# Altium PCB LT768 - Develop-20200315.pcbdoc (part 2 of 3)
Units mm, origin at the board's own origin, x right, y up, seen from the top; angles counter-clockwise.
Board outline 114.72 x 114.74 mm, 2 copper layers (Top Layer, Bottom Layer); 164 components, 138 nets, 704 pads, 858 vias.
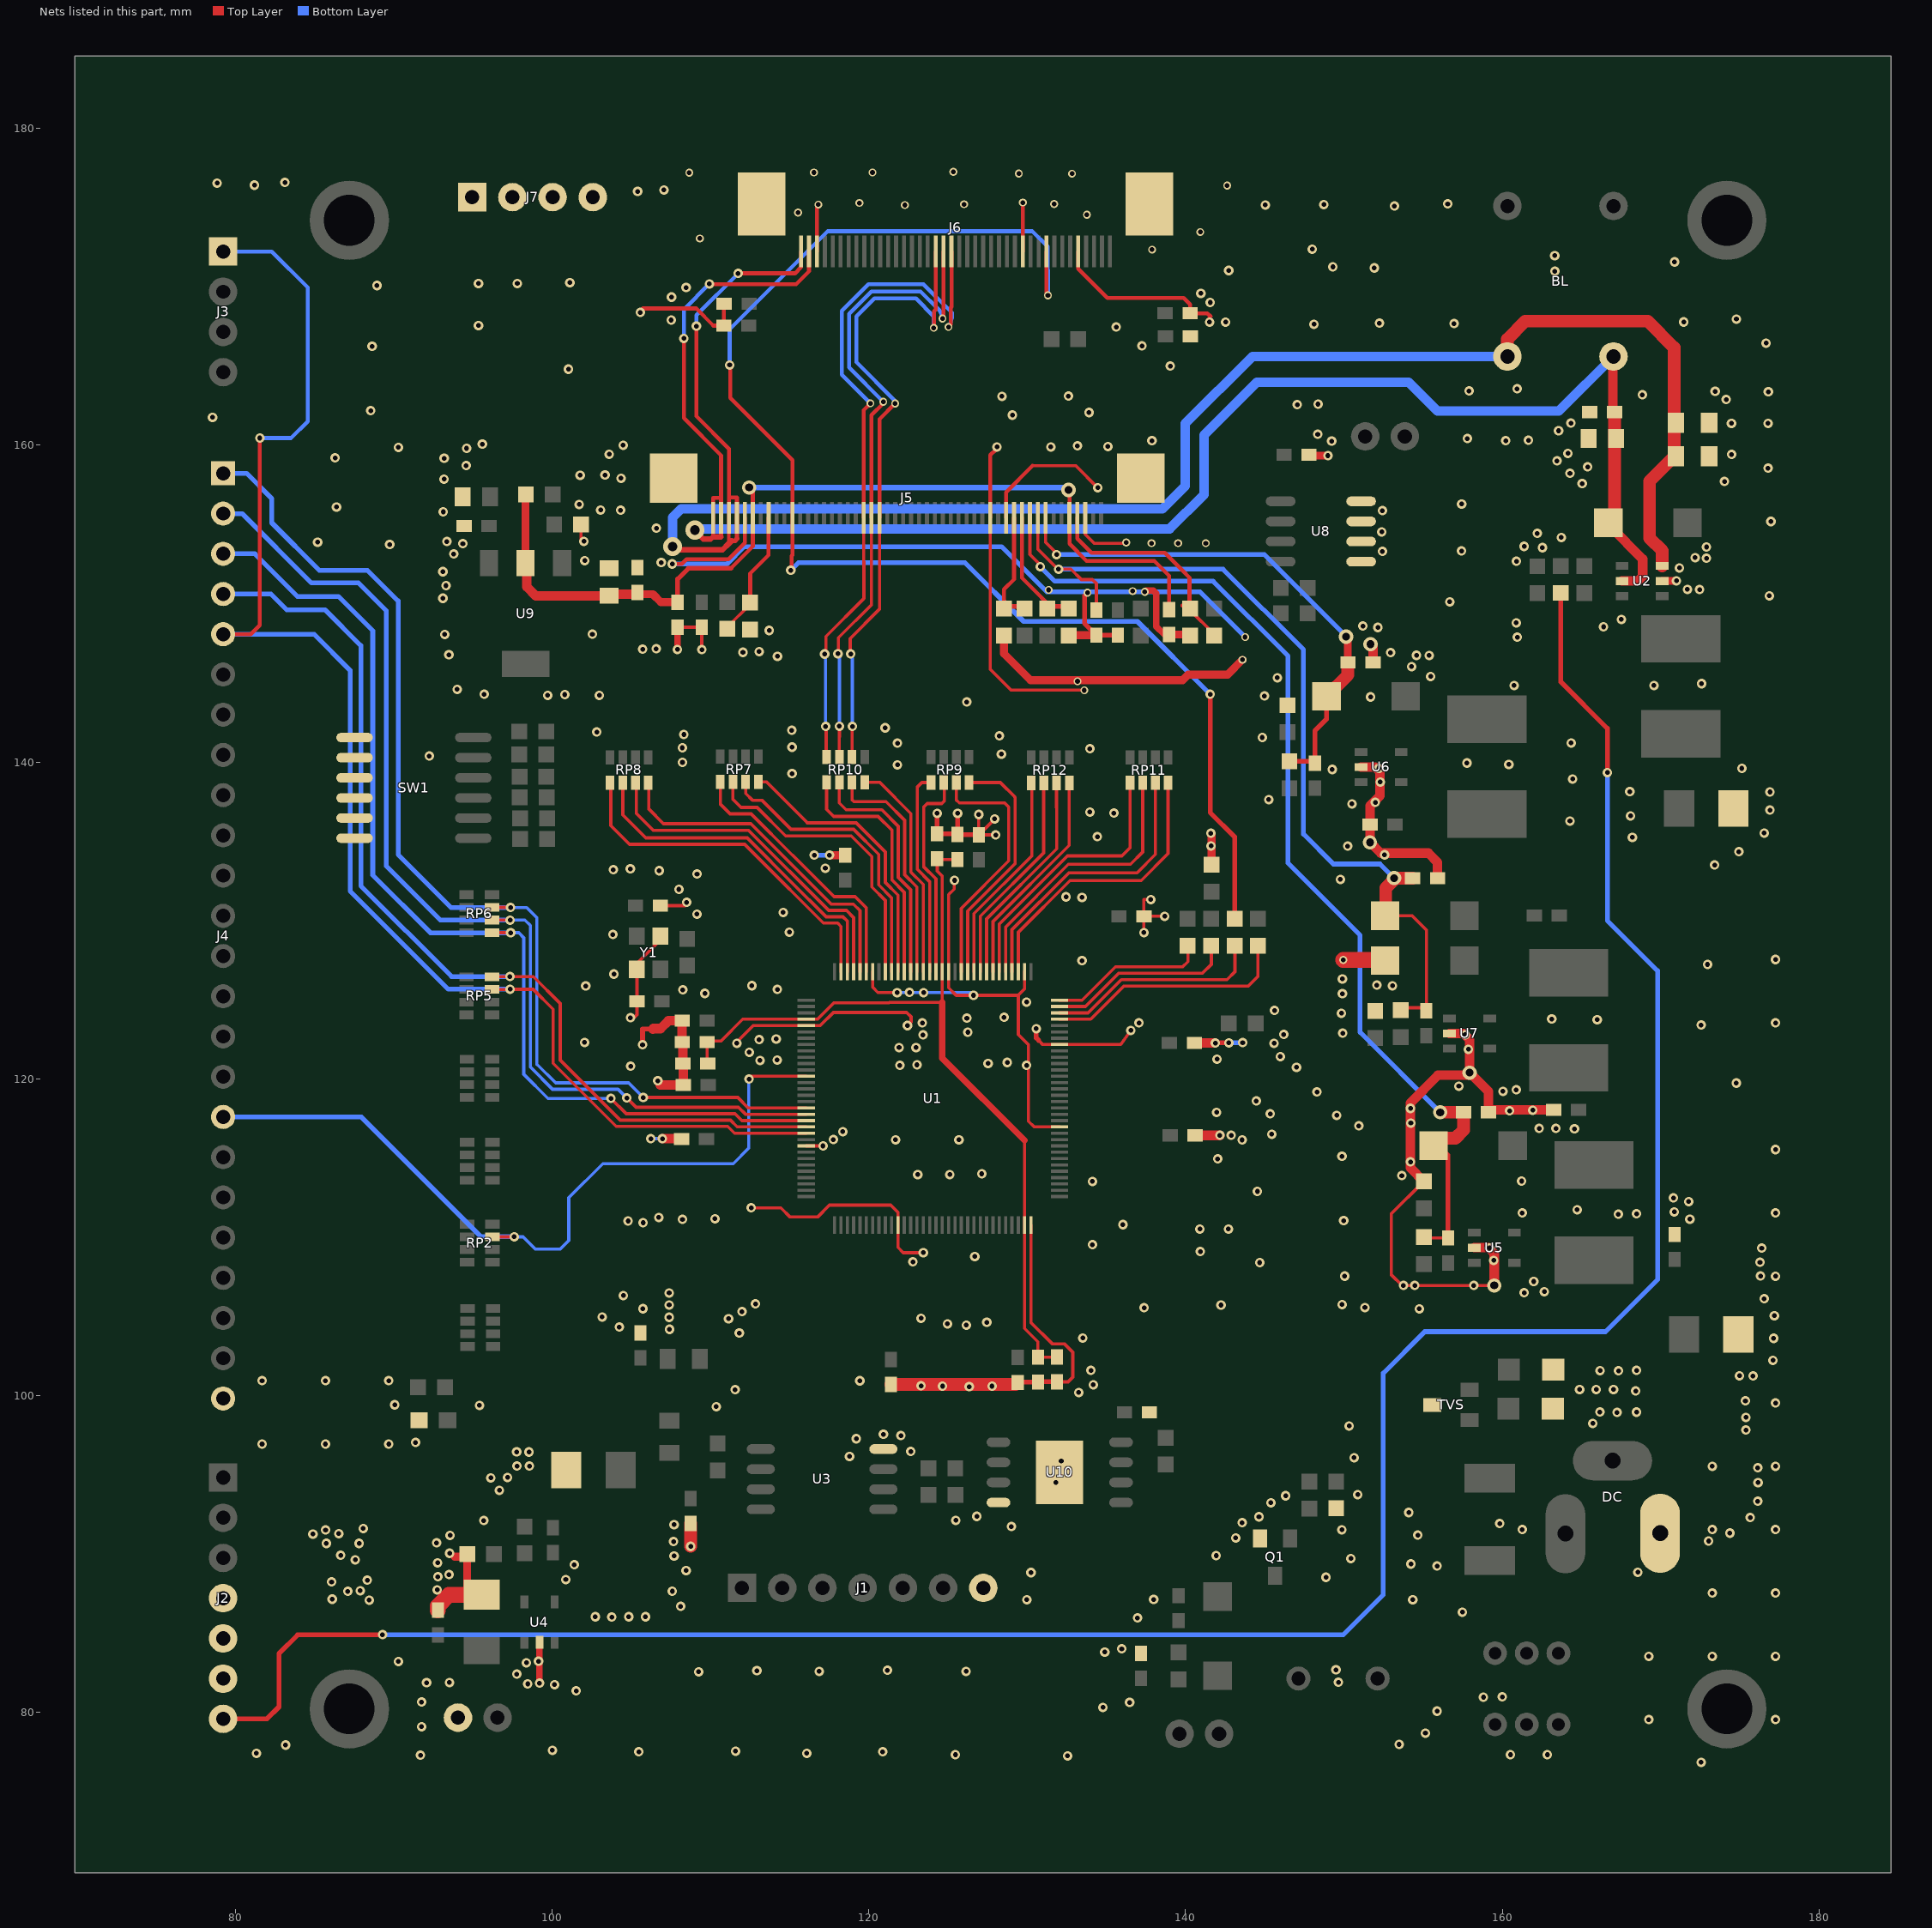
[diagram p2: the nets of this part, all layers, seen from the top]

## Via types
v1: diameter 0.6, hole 0.3, Top Layer to Bottom Layer, 743 vias
v2: diameter 0.5, hole 0.3, Top Layer to Bottom Layer, 82 vias
v3: diameter 0.9, hole 0.5, Top Layer to Bottom Layer, 20 vias
v4: diameter 1.2, hole 0.6, Top Layer to Bottom Layer, 7 vias
v5: diameter 0.8, hole 0.4, Top Layer to Bottom Layer, 6 vias

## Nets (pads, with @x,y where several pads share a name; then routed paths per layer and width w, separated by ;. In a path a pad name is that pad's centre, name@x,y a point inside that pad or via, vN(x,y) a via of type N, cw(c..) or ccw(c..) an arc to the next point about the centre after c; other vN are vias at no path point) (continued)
G5: J5.22 J6.18 RP10.6 | length 41.2
  Top Layer w0.2: v1(118.86,146.83) 118.82,146.83 118.82,147.8 120.67,149.65 J5.22@120.67,155.43 ; RP10.6@118.936,140.667 118.95,140.667 118.95,142.25 v1(118.96,142.25)
  Top Layer w0.25: J5.22@120.67,155.43 120.67,161.65 v2(121.66,162.64) ; v2(124.1,167.42) 124.12,167.44 124.12,168.47 124.22,168.57 J6.18@124.22,172.24
  Bottom Layer w0.2: v1(118.86,146.83) 118.78,146.73 118.96,146.55 v1(118.96,142.25)
  Bottom Layer w0.25: v2(121.66,162.64) 121.66,162.813 119.22,165.253 119.22,168.142 120.348,169.27 122.971,169.27 124.1,168.141 v2(124.1,167.42)
G6: J5.21 J6.19 RP10.7 | length 41.5
  Top Layer w0.2: v1(118.05,146.84) 118.05,146.9 118.08,146.93 118.08,147.85 120.17,149.94 J5.21@120.17,155.43 ; RP10.7@118.136,140.667 118.136,141.602 118.14,141.605 v1(118.14,142.26)
  Top Layer w0.25: J5.21@120.17,155.43 120.17,161.907 120.91,162.647 v2(120.91,162.75) ; v2(124.65,168.01) 124.68,168.01 124.72,168.05 J6.19@124.72,172.24
  Bottom Layer w0.2: v1(118.05,146.84) 118.14,146.83 v1(118.14,142.26)
  Bottom Layer w0.25: v2(120.91,162.75) 118.75,164.91 118.75,167.64 118.75,168.308 120.162,169.72 123.265,169.72 124.42,168.565 124.715,168.047 v2(124.65,168.01)
G7: J5.20 J6.20 RP10.8 | length 44.3
  Top Layer w0.2: v1(117.21,146.82) 117.28,146.89 117.29,146.89 117.29,147.934 119.69,150.334 119.69,150.83 119.69,152.644 119.67,152.664 J5.20@119.67,155.43 ; v1(117.27,142.25) 117.27,142.3 117.31,142.3 117.31,140.667 RP10.8@117.336,140.667
  Top Layer w0.25: J5.20@119.67,155.43 119.67,162.22 v2(120.1,162.65) ; v2(125.03,167.47) 125.18,167.62 125.18,168.7 125.22,168.74 J6.20@125.22,172.24
  Bottom Layer w0.2: v1(117.21,146.82) 117.31,146.75 117.27,146.75 v1(117.27,142.25)
  Bottom Layer w0.25: v2(120.1,162.65) 118.3,164.45 118.3,168.494 119.976,170.17 123.451,170.17 125.24,168.381 125.24,168.034 125.09,167.454 v2(125.03,167.47)
GND: C1.2 C2.2 C3.2 C4.2 C5.2 C6.2 C7.2 C8.2 C9.2 C10.2 C11.2 C12.2 C13.2 C14.2 C15.2 C16.2 C17.1 C18.2 C19.2 C20.2 C21.2 C22.1 C24.2 C25.2 C32.2 C33.2 C40.2 C47.2 C48.2 C49.2 C52.2 C53.2 C54.2 C55.2 C56.2 C58.2 C59.2 C60.1 C61.2 C63.2 C65.2 C66.2 C68.2 C70.2 C71.2 C72.2 C73.2 C80.2 C81.2 D5.2 D7.A D8.A DC.1 J1.7 J2.4 J2.5 J2.6 J4.24 J5.5 J5.36 J5.38 J5.48 J5.51 J5.52 J6.3 J6.29 J6.36 J6.41 J6.42 J7.1 J7.2 J7.3 J7.4 LED1.2 POWER.1 Q1.2 R2.1 R4.1 R6.1 R8.1 R20.1 R23.2 R47.2 R52.2 R53.2 R55.2 R57.2 R59.2 R67.2 SW1.1 SW1.2 SW1.3 SW1.4 SW1.5 SW1.6 TVS.3 U1.5 U1.24 U1.43 U1.64 U1.76 U1.89 U1.98 U1.110 U1.122 U2.2 U3.4 U4.2 U5.2 U6.2 U7.2 U8.1 U8.2 U8.3 U8.4 U10.4 U10.9 Y1.2 Y1.4 | length 505.7
  Top Layer w0.2: Y1.2@106.84,129.01 106.84,128.77 105.34,127.27 105.34,126.98 105.363,126.957 C17.1@105.363,124.89 ; C71.2@107.92,148.517 C72.2@109.45,148.517 ; C3.2@108.153,116.22 C3.2@108.173,116.19 ; U1.122@120.24,126.76 120.24,125.78 120.57,125.45 121.79,125.45 v1(121.79,125.44) ; U1.98@129.84,126.76 129.84,125.68 129.44,125.28 ; U1.64@130.24,110.76 130.24,104.6 131.575,103.265 132.34,103.265 132.88,102.725 132.88,101.16 132.58,100.86 C13.2@131.88,100.863 ; R8.1@132.63,147.99 R8.1@132.654,148.014 ; R4.1@140.227,148.053 R4.1@140.29,147.99 ; R57.2@155.046,113.519 152.99,111.462 152.99,107.63 153.67,106.95 v1(153.76,106.95) v1(154.48,106.95) v1(158.2,106.95) v3(159.5,106.95) ; v1@101.83,153.94 R47.2@101.83,155 v1@101.83,153.94 ; v1@101.83,153.94 v1(102.01,153.94) v1@101.83,153.94 ; v1@105.017,123.917 v1@105.23,123.917 ; v1@105.017,123.917 v1(104.95,123.85) v1@105.017,123.917 ; v1@105.017,123.917 v1@105.23,123.917 ; v1@105.23,123.917 105.363,124.05 ; v1@105.23,123.917 105.363,124.05 ; 105.363,124.05 C17.1@105.363,124.89 ; 105.363,124.05 C17.1@105.363,124.89 ; v1@108.4,130.93 C16.2@106.837,130.93 v1@108.4,130.93 ; v1@108.4,130.93 v1@108.54,131.07 ; v1@108.4,130.93 v1@108.54,131.07 ; v1@108.54,131.07 v1(108.49,131.14) v1@108.54,131.07 ; C72.2@109.45,148.517 109.45,147.1 C72.2@109.45,148.517 ; v1@111.66,122.32 112.7,123.36 ; v1@111.66,122.32 v1(111.66,122.24) v1@111.66,122.32 ; v1@111.66,122.32 112.7,123.36 ; 112.7,123.36 U1.5@116.04,123.36 ; 112.7,123.36 U1.5@116.04,123.36 ; 114.45,111.85 115.03,111.27 ; 114.45,111.85 v1(112.57,111.85) 114.45,111.85 ; 114.45,111.85 115.03,111.27 ; 115.03,111.27 116.76,111.27 ; 115.03,111.27 116.76,111.27 ; U1.5@116.04,123.36 116.93,123.36 ; U1.5@116.04,123.36 116.93,123.36 ; 116.76,111.27 117.51,112.02 ; 116.76,111.27 117.51,112.02 ; 116.93,123.36 117.76,124.19 ; 116.93,123.36 117.76,124.19 ; 117.51,112.02 121.38,112.02 ; 117.51,112.02 121.38,112.02 ; 117.76,124.19 122.39,124.19 ; 117.76,124.19 122.39,124.19 ; 121.38,112.02 121.84,111.56 ; 121.38,112.02 121.84,111.56 ; 121.84,109.35 U1.43@121.84,110.76 ; 121.84,109.35 122.17,109.02 ; 121.84,109.35 122.17,109.02 ; 121.84,109.35 U1.43@121.84,110.76 ; U1.43@121.84,110.76 121.84,111.56 ; U1.43@121.84,110.76 121.84,111.56 ; 122.17,109.02 v1(123.44,109.02) 122.17,109.02 ; 122.39,124.19 122.67,123.91 ; 122.39,124.19 122.67,123.91 ; 122.67,123.59 122.67,123.91 ; 122.67,123.59 v1(122.44,123.36) 122.67,123.59 ; 122.67,123.59 122.67,123.91 ; U1.110@125.04,126.76 125.04,125.75 125.52,125.27 v1(126.61,125.27) ; U1.110@125.04,126.76 125.04,131.63 ; U1.110@125.04,126.76 125.04,131.63 ; 125.04,131.63 125.39,131.98 ; 125.04,131.63 125.39,131.98 ; 125.39,131.98 v1@125.39,132.53 ; 125.39,131.98 v1@125.39,132.53 ; v1@125.39,132.53 v1(125.41,132.53) v1@125.39,132.53 ; v1(126.61,125.27) 129.43,125.27 ; v1(126.61,125.27) 129.43,125.27 ; C8.2@126.944,135.4 C8.2@126.944,135.404 ; C8.2@126.944,135.4 C8.2@126.944,135.404 ; C8.2@126.944,135.4 v1(128.01,135.4) C8.2@126.944,135.4 ; C8.2@126.944,135.404 v1(127.95,136.41) C8.2@126.944,135.404 ; C8.2@126.944,135.404 v1@126.944,136.686 ; C8.2@126.944,135.404 v1@126.944,136.686 ; v1@126.944,136.686 v1(126.94,136.69) v1@126.944,136.686 ; 127.67,145.86 J5.36@127.67,155.43 127.67,145.86 ; 127.67,145.86 128.98,144.55 ; 127.67,145.86 128.98,144.55 ; 128.98,144.55 v2@133.59,144.55 ; 128.98,144.55 v2@133.59,144.55 ; 129.43,125.27 129.44,125.28 ; 129.43,125.27 129.44,125.28 ; 129.44,122.79 130.08,122.15 ; 129.44,122.79 129.44,125.28 ; 129.44,122.79 130.08,122.15 ; 129.44,122.79 129.44,125.28 ; 129.44,122.79 130.08,122.15 ; 129.44,122.79 129.44,125.28 ; 130.08,117.32 130.44,116.96 ; 130.08,117.32 130.08,122.15 ; 130.08,117.32 130.44,116.96 ; 130.08,117.32 130.08,122.15 ; 130.08,117.32 130.44,116.96 ; 130.08,117.32 130.08,122.15 ; 130.44,116.96 U1.76@132.04,116.96 ; 130.44,116.96 U1.76@132.04,116.96 ; 130.44,116.96 U1.76@132.04,116.96 ; 130.99,122.16 U1.89@132.04,122.16 ; 130.99,122.16 130.73,122.42 130.99,122.16 ; 130.99,122.16 U1.89@132.04,122.16 ; U1.89@132.04,122.16 135.91,122.16 ; U1.89@132.04,122.16 135.91,122.16 ; 133.072,158.708 130.337,158.708 133.072,158.708 ; 133.072,158.708 v1(134.46,157.32) 133.072,158.708 ; v2@133.59,144.55 v2(133.61,144.53) v2@133.59,144.55 ; 133.67,154.379 J5.48@133.67,155.43 133.67,154.379 ; 133.67,154.379 134.239,153.81 ; 133.67,154.379 134.239,153.81 ; 134.239,153.81 v2@136.268,153.81 ; 134.239,153.81 v2@136.268,153.81 ; 135.91,122.16 v1(136.55,123.05) 135.91,122.16 ; v2@136.268,153.81 v2@136.268,153.852 ; v2@136.268,153.81 v2@136.268,153.852 ; v2@136.268,153.852 v2(136.26,153.86) v2@136.268,153.852 ; C32.2@137.371,130.243 C32.2@137.388,130.26 ; C32.2@137.371,130.243 C32.2@137.388,130.26 ; C32.2@137.371,130.243 137.371,131.32 ; C32.2@137.371,130.243 137.371,131.32 ; 137.371,131.32 v1(137.81,131.32) 137.371,131.32 ; C32.2@137.388,130.26 v1(138.69,130.26) C32.2@137.388,130.26 ; v1(93.53,90.04) 93.85,89.82 v1(93.53,90.04) ; v1(107.91,147.11) 107.92,147.11 v1(107.91,147.11) ; U1.24@116.04,115.76 v1(117.11,115.76) U1.24@116.04,115.76 ; v1(137.37,129.23) 137.37,130.242 v1(137.37,129.23) ; v1(141.6,135.5) 141.64,135.46 v1(141.6,135.5) ; v1(142.17,116.43) 142.174,116.426 v1(142.17,116.43) ; C80.2@147.8,159.402 147.93,159.35 C80.2@147.8,159.402
  Top Layer w0.25: v1(105.57,168.39) 105.57,168.48 105.73,168.64 109.1,168.64 110.18,167.56 C18.2@110.843,167.56 110.843,168.91 C19.2@110.863,168.93 ; v1(107.59,152.51) 108.186,152.51 108.486,152.81 111.151,152.81 112.17,153.829 J5.5@112.17,155.43 ; J6.3@116.72,172.24 116.72,175.2 v2(116.81,175.2) ; J5.36@127.67,155.43 127.67,159.38 128.01,159.72 128.01,159.82 v1(128.09,159.9) ; J6.29@129.72,172.24 v2(129.72,175.33) ; J6.36@133.22,172.24 133.22,171.15 135.07,169.3 139.89,169.3 140.287,168.903 C21.2@140.287,168.34 141.38,168.34 141.59,168.13 141.52,168.06 v1(141.52,167.78) ; v1(117.52,134.12) v1@117.522,134.118 ; v1(117.52,134.12) v1@117.522,134.118 ; v1(117.52,134.12) v1@117.522,134.118 ; 128.67,157.041 J5.38@128.67,155.43 128.67,157.041 ; 128.67,157.041 130.337,158.708 128.67,157.041
  Top Layer w0.3: C10.2@108.213,122.326 C10.2@108.256,122.283 ; C11.2@108.256,120.972 C11.2@108.286,120.942 ; C8.2@126.944,135.4 126.923,135.421 C14.2@125.605,135.421 ; C5.2@129.27,100.703 129.39,100.823 C5.2@129.4,100.823 129.42,100.843 C12.2@130.68,100.843 130.7,100.863 C13.2@131.88,100.863 ; C33.2@135.72,148.014 C70.2@134.37,148.014 ; C7.2@140.558,122.256 C7.2@140.562,122.26 ; 105.71,123.137 106.357,123.139 105.71,123.137 ; 105.71,123.137 v1(105.71,122.15) 105.71,123.137 ; v1@106.66,119.771 106.82,119.611 v1@106.66,119.771 ; v1@106.66,119.771 v1@106.66,119.86 ; v1@106.66,119.771 v1@106.66,119.86 ; v1@106.66,119.86 v1(106.67,119.87) v1@106.66,119.86 ; C15.2@124.308,135.468 124.308,136.758 C15.2@124.308,135.468 ; C15.2@124.308,135.468 125.558,135.468 C14.2@125.605,135.421 ; C14.2@125.605,135.421 v1@125.605,136.755 ; C14.2@125.605,135.421 v1@125.605,136.755 ; v1@125.605,136.755 v1(125.61,136.76) v1@125.605,136.755 ; 130.57,122.58 130.73,122.42 130.57,122.58 ; 130.57,122.58 v1(130.57,123.16) 130.57,122.58 ; 133.62,148.764 C70.2@134.37,148.014 ; 133.62,148.764 133.62,150.5 ; 133.62,148.764 133.62,150.5 ; 133.62,148.764 C70.2@134.37,148.014 ; 133.62,150.5 v2(133.81,150.69) 133.62,150.5 ; v1@141.89,122.27 v1(141.88,122.26) v1@141.89,122.27 ; v1@141.89,122.27 v1(142.74,122.27) v1@141.89,122.27
  Top Layer w0.4: v2(137.43,150.75) 137.51,150.83 137.96,150.83 138.16,150.63 138.16,148.553 138.66,148.053 C73.2@138.965,148.053 ; v1(99.2,81.84) U4.2@99.203,84.419 v1(99.2,81.84) ; v1@107.92,147.11 C71.2@107.92,148.517 v1@107.92,147.11
  Top Layer w0.5: C59.2@94.85,87.418 94.633,87.635 R53.2@94.633,89.973 ; R8.1@132.654,148.014 C70.2@134.37,148.014 ; C73.2@138.965,148.053 R4.1@140.227,148.053 ; R53.2@94.633,89.82 R53.2@94.633,89.973 ; R53.2@94.633,89.82 93.85,89.82 R53.2@94.633,89.82 ; R53.2@94.633,89.82 R53.2@94.633,89.973 ; v1@117.522,134.118 C9.2@118.509,134.118 ; v1@117.522,134.118 C9.2@118.509,134.118 ; v1@117.522,134.118 C9.2@118.509,134.118 ; 128.53,146.85 R6.1@128.53,147.99 128.53,146.85 ; 128.53,146.85 130.21,145.17 ; 128.53,146.85 130.21,145.17 ; 130.21,145.17 v2@133.18,145.17 ; 130.21,145.17 v2@133.18,145.17 ; v2@133.18,145.17 v2(133.18,145.1) v2@133.18,145.17 ; v2@133.18,145.17 139.82,145.17 ; v2@133.18,145.17 139.82,145.17 ; 139.82,145.17 140.17,145.52 ; 139.82,145.17 140.17,145.52 ; 140.17,145.52 142.66,145.52 ; 140.17,145.52 142.66,145.52 ; 142.66,145.52 v2(143.6,146.46) 142.66,145.52 ; U2.2@170.11,151.44 U2.2@170.11,151.43 U2.2@170.11,151.44 ; U2.2@170.11,151.44 v1(171,151.44) U2.2@170.11,151.44 ; R20.1@141.64,133.52 141.64,135.46 R20.1@141.64,133.52 ; C80.2@147.93,159.35 v1(148.99,159.35) C80.2@147.93,159.35 ; D5.2@152.61,127.47 152.61,127.51 D5.2@152.61,127.47
  Top Layer w0.6: v1(106.96,116.22) C3.2@108.153,116.22 ; C10.2@108.213,122.326 C2.2@108.213,123.666 ; C11.2@108.256,120.972 C10.2@108.256,122.283 ; C11.2@108.286,120.942 C40.2@108.286,119.611 ; C7.2@140.562,122.26 v1(141.88,122.26) ; U6.2@151.082,139.682 151.982,139.682 152.27,139.394 152.27,137.87 151.655,137.255 C63.2@151.655,136.062 151.655,134.935 v3(151.65,134.93) 152.33,134.25 155.33,134.25 155.917,133.663 C68.2@155.917,132.66 ; R57.2@155.046,113.519 154.193,114.372 154.193,114.75 154.193,118.463 155.95,120.22 157.94,120.22 v3(157.94,120.39) ; U5.2@158.236,109.329 159.136,109.329 159.5,108.965 v3(159.5,106.95) ; C66.2@163.251,118.033 159.278,118.033 C58.2@159.134,117.889 159.134,119.196 v3(157.94,120.39) ; 106.388,123.17 106.854,123.17 ; 106.388,123.17 106.357,123.139 106.388,123.17 ; 106.388,123.17 106.854,123.17 ; 106.854,123.17 107.35,123.666 ; 106.854,123.17 107.35,123.666 ; 107.35,123.666 C2.2@108.213,123.666 ; 107.35,123.666 C2.2@108.213,123.666 ; C40.2@108.286,119.611 106.82,119.611 C40.2@108.286,119.611 ; v3@151.84,147.28 C65.2@151.84,146.302 v3@151.84,147.28 ; v3@151.84,147.28 v3(151.68,147.44) v3@151.84,147.28 ; v1@157.57,122.86 157.94,122.49 ; v1@157.57,122.86 U7.2@156.67,122.86 v1@157.57,122.86 ; v1@157.57,122.86 157.94,122.49 ; v3(157.94,120.39) 157.94,122.49 ; v3(157.94,120.39) 157.94,122.49 ; C6.2@140.606,116.426 142.174,116.426 C6.2@140.606,116.426
  Top Layer w0.8: C4.2@121.4,100.703 C5.2@129.27,100.703 ; v1(108.75,90.47) C24.2@108.751,91.916 v1(108.75,90.47)
  Top Layer w1: C59.2@95.547,87.418 C59.2@94.85,87.418 ; C60.1@92.78,86.708 93.49,87.418 ; C60.1@92.78,86.708 C60.1@92.78,86.447 C60.1@92.78,86.708 ; C60.1@92.78,86.708 93.49,87.418 ; 93.49,87.418 C59.2@94.85,87.418 ; 93.49,87.418 C59.2@94.85,87.418 ; v2(149.96,127.51) 152.61,127.51 v2(149.96,127.51)
  Bottom Layer w0.2: v1(106.23,116.22) v1(106.96,116.22) ; v1(121.79,125.44) v1(123.46,125.44) 126.41,125.44 126.61,125.24 v1(126.61,125.27)
  Bottom Layer w0.3: v1(107.59,152.51) 111.042,152.51 112.132,153.6 128.385,153.6 131.235,150.75 v2(137.43,150.75) ; v1(116.55,134.12) v1(117.52,134.12) ; v1(116.55,134.12) v1(117.52,134.12) ; v1(116.55,134.12) v1(117.52,134.12) ; v2(137.43,150.75) 140.91,150.75 ; v2(137.43,150.75) 140.91,150.75 ; 140.91,150.75 v2(143.77,147.89) 140.91,150.75 ; v1(142.74,122.27) v1(143.61,122.28) v1(142.74,122.27)
  other v1: 172.565,76.842 132.55,77.24 91.68,77.29 125.47,77.32 160.52,77.32 162.85,77.32 81.32,77.41 116.08,77.41 105.47,77.5 120.87,77.5 111.58,77.54 100.02,77.6 83.16,77.93 153.49,77.97 155.15,78.68 91.75,79.09 169.262,79.531 177.262,79.531 155.89,80.07 134.78,80.31 136.47,80.62 91.75,80.64 158.81,80.95 160.01,80.97 101.52,81.35 100.15,81.74 98.46,81.79 92.07,81.86 93.51,81.88 149.66,81.89 97.77,82.41 109.25,82.55 116.86,82.58 126.14,82.58 112.93,82.62 121.17,82.65 149.5,82.68 98.37,83.12 90.29,83.2 99.14,83.22 169.262,83.531 173.262,83.531 177.262,83.531 134.9,83.8 135.97,84 136.97,85.95 103.77,86.01 102.72,86.03 104.84,86.03 105.89,86.03 157.49,86.32 108.12,86.69 88.443,87.076 129.98,87.1 154.35,87.1 137.99,87.12 86.11,87.14 173.262,87.531 177.262,87.531 87.09,87.63 107.59,87.64 87.88,87.67 92.74,87.73 86.07,88.23 88.32,88.34 100.86,88.38 148.87,88.52 92.78,88.56 93.49,88.69 130.24,88.82 168.565,88.842 108.46,88.95 155.89,89.23 101.4,89.31 154.24,89.36 92.77,89.44 87.57,89.62 150.44,89.71 107.7,89.87 141.94,89.89 86.64,89.91 85.74,90.66 87.81,90.66 92.7,90.7 107.67,90.78 173.04,90.81 143.17,91.01 93.55,91.17 154.67,91.18 84.89,91.25 86.52,91.28 174.38,91.31 85.69,91.51 149.87,91.52 161.262,91.531 173.262,91.531 177.262,91.531 88.07,91.6 129,91.72 107.7,91.85 159.84,91.91 143.58,91.97 95.684,92.103 125.49,92.12 175.66,92.29 144.64,92.34 126.82,92.37 154.1,92.61 145.39,93.23 176.14,93.32 146.32,93.67 150.88,93.74 96.67,94.01 176.16,94.5 131.8,94.52 96.13,94.8 97.18,94.83 176.14,95.44 97.78,95.54 98.56,95.54 173.262,95.531 177.262,95.531 132.15,95.86 150.65,96.07 118.78,96.15 98.54,96.43 97.76,96.44 122.65,96.47 81.68,96.932 85.68,96.932 89.68,96.932 91.37,97.04 119.21,97.27 122.03,97.47 120.92,97.55 175.39,97.82 150.33,98.08 165.72,98.24 175.39,98.62 167.25,98.93 166.172,98.961 168.49,98.95 110.36,99.3 95.41,99.38 90.06,99.41 177.262,99.531 175.36,99.66 133.26,100.19 168.43,100.29 111.56,100.37 164.89,100.38 165.94,100.38 167.03,100.38 126.34,100.56 124.65,100.59 127.78,100.59 123.3,100.61 134.18,100.68 81.68,100.932 85.68,100.932 89.68,100.932 119.43,100.93 175.84,101.23 174.99,101.25 167.35,101.56 166.18,101.57 134.03,101.59 168.48,101.59 177.1,102.22 177.14,103.61 133.51,103.63 111.82,103.94 107.41,104.18 104.24,104.32 126.16,104.44 124.96,104.52 127.45,104.62 111.14,104.85 123.3,104.88 107.39,104.94 103.16,104.96 177.19,105.04 111.993,105.296 154.76,105.47 105.73,105.48 137.38,105.54 151.33,105.55 107.39,105.72 142.24,105.71 149.89,105.74 112.84,105.78 176.55,106.11 104.5,106.31 107.39,106.48 161.39,106.49 162.66,106.56 161.99,107.2 150.05,107.54 176.31,107.55 177.262,107.531 144.69,108.392 176.28,108.41 122.78,108.44 159.46,108.53 126.69,108.78 140.93,109.09 159.2,109.32 176.39,109.31 134.12,109.522 140.91,110.51 142.71,110.51 136.04,110.79 105.74,110.912 104.8,111.02 149.99,111.04 108.23,111.12 171.85,111.13 110.28,111.16 106.73,111.24 167.33,111.45 168.48,111.47 161.262,111.531 177.262,111.531 170.87,111.6 164.73,111.73 171.78,112.24 170.81,112.48 144.54,112.89 134.12,113.522 161.22,113.54 153.66,113.88 123.09,113.95 125.11,113.95 127.13,114 154.21,114.75 142.03,114.94 149.88,115.1 177.262,115.531 143.58,116.14 117.76,116.16 121.69,116.142 125.69,116.142 106.23,116.22 142.88,116.43 145.45,116.5 118.36,116.66 164.565,116.842 162.34,116.87 163.39,116.87 150.95,117.03 154.23,117.2 149.55,117.69 145.35,117.79 141.96,117.88 160.47,117.98 161.93,118.02 154.21,118.13 144.47,118.6 148.3,119.17 160.05,119.21 160.89,119.3 157.262,119.531 174.78,119.73 147.01,120.72 104.96,120.79 121.96,120.842 129.96,120.842 123.04,120.88 127.53,120.97 128.74,121.03 113.13,121.16 114.21,121.19 141.99,121.24 145.99,121.4 112.45,121.67 157.87,121.86 121.91,121.97 122.98,121.97 141.88,122.26 141.88,122.26 145.59,122.24 142.74,122.27 102.05,122.3 113.07,122.47 114.15,122.51 123.42,122.77 157.66,122.78 146.2,122.8 149.93,122.88 126.25,122.94 172.56,123.39 123.38,123.53 137.06,123.53 177.262,123.531 166,123.73 163.13,123.77 126.19,123.83 128.54,123.88 149.85,124.14 145.62,124.31 129.96,124.842 126.61,125.27 149.91,125.37 109.64,125.39 122.57,125.45 108.25,125.62 114.22,125.64 102.12,125.86 112.61,125.88 153.07,125.87 152.08,125.91 149.91,126.31 103.9,126.61 172.97,127.22 133.463,127.456 177.262,127.531 103.83,129.11 114.98,129.26 109.14,130.4 114.59,130.5 133.463,131.456 132.453,131.485 108.01,131.96 149.78,132.59 109.15,132.93 106.76,133.14 103.86,133.2 104.94,133.25 117.25,133.29 173.42,133.5 116.55,134.12 117.52,134.12 152.57,134.14 174.95,134.34 141.61,134.7 150.243,134.696 168.22,135.24 134.43,135.29 176.55,135.52 164.28,136.27 168.11,136.6 124.31,136.76 135.48,136.78 133.96,136.842 176.91,136.97 150.51,137.36 151.99,137.45 145.26,137.63 176.91,138.11 168.06,138.13 152.3,138.74 164.45,138.93 115.15,139.27 149.262,139.531 152.21,139.6 175.14,139.6 121.81,139.82 160.42,139.85 157.77,139.94 108.23,139.98 92.24,140.38 128.37,140.5 133.96,140.842 108.22,140.9 115.15,140.94 121.81,141.19 164.36,141.2 144.85,141.55 128.24,141.65 108.32,141.74 102.82,141.9 115.13,142 121.03,142.16 126.18,143.79 151.69,144.11 144.99,144.17 99.72,144.21 102.98,144.21 95.71,144.28 100.8,144.26 94,144.59 160.75,144.84 169.58,144.84 172.59,144.95 145.8,145.32 155.48,145.4 154.28,146.03 114.23,146.68 154.59,146.74 155.39,146.73 93.48,146.77 152.95,146.91 112.05,146.93 113.07,146.97 109.45,147.1 105.72,147.13 106.57,147.15 160.95,147.88 93.22,148.06 102.54,148.07 113.71,148.31 152.15,148.5 166.4,148.54 151.2,148.59 160.89,148.79 167.52,149.01 156.69,150.12 93.1,150.34 176.87,150.5 171.7,150.9 172.47,150.89 93.3,151.14 93.1,152.02 171.19,152.26 106.89,152.6 160.9,152.68 102.06,152.72 172.9,152.87 172.18,152.91 93.78,153.14 152.43,153.3 157.43,153.33 162.54,153.54 172.9,153.58 161.39,153.62 89.74,153.74 94.36,153.79 85.19,153.88 93.35,153.93 163.73,154.18 162.21,154.44 152.39,154.53 106.58,154.77 176.97,155.19 93.12,155.8 152.44,155.88 103.06,155.91 104.32,155.9 86.38,156.11 101.71,156.27 157.44,156.29 165.05,157.58 174.04,157.72 93.17,157.87 104.35,157.92 101.77,158.11 103.34,158.12 164.28,158.23 176.79,158.56 165.4,158.64 94.57,158.72 163.46,159.02 93.18,159.18 86.29,159.21 174.49,159.42 103.6,159.44 164.15,159.49 94.6,159.81 90.29,159.87 131.49,159.9 135.1,159.92 133.17,159.97 104.49,160.01 95.59,160.07 149.23,160.26 137.88,160.29 160.22,160.29 161.66,160.32 157.8,160.43 148.35,160.7 163.56,160.92 164.34,161.4 174.48,161.39 176.79,161.39 78.55,161.77 129.07,161.91 133.9,162.07 88.54,162.19 147.06,162.57 148.37,162.6 174.15,162.89 128.41,163.09 132.61,163.11 168.85,163.19 176.81,163.38 173.45,163.41 157.91,163.43 160.94,163.57 101.03,164.81 139.04,165.01 88.63,166.25 137.25,166.28 176.67,166.45 135.62,167.47 95.35,167.56 148.11,167.65 156.96,167.69 152.25,167.71 142.53,167.78 171.47,167.79 107.52,167.91 174.79,167.97 141.56,169.02 107.54,169.36 140.97,169.6 108.46,169.96 88.93,170.09 95.35,170.22 97.8,170.22 101.12,170.27 163.33,170.99 142.73,171.04 151.92,171.2 149.31,171.27 170.88,171.58 163.32,171.98 148,172.39 153.19,175.11 145.04,175.18 148.74,175.2 156.56,175.24 105.4,176.03 107.06,176.12 81.2,176.43 78.84,176.56 83.12,176.6
  other v2: 137.43,150.75 136.66,150.79 131.36,150.87 137.85,153.82 139.53,153.82 141.28,153.82 137.89,172.36 109.33,173.06 140.93,173.47 133.77,174.56 115.53,174.7 122.28,175.17 126.02,175.22 131.7,175.24 119.41,175.3 142.63,176.4 132.83,177.15 129.47,177.16 108.66,177.22 116.53,177.23 120.23,177.23 125.34,177.27
  other v3: 157.94,120.39
HSYNC: J5.11 J6.32 R19.1 | length 91
  Top Layer w0.25: v1(111.21,165.07) 111.21,165.1 111.24,165.13 111.24,163 115.17,159.07 J5.11@115.17,155.43 115.17,153.062 115.13,153.022 115.13,152.11 v1(115.07,152.11) ; J6.32@131.22,172.24 131.22,169.6 131.31,169.51 v2(131.31,169.47)
  Top Layer w0.3: v1(141.56,144.28) 141.56,136.82 143.1,135.28 R19.1@143.1,130.1
  Bottom Layer w0.25: v1(111.21,165.07) 111.21,167.33 117.4,173.52 130.33,173.52 131.3,172.55 131.3,171.077 131.31,171.067 v2(131.31,169.47)
  Bottom Layer w0.3: v1(115.07,152.11) 115.56,152.6 126.06,152.6 129.78,148.88 136.96,148.88 v1(141.56,144.28)
LCD-AVDD: C64.1 C65.1 D3.2 J5.43 R58.1 | length 38.3
  Top Layer w0.2: J5.43@131.17,155.43 131.17,153.87 131.883,153.157 131.86,153.133 v1(131.86,153.1) ; C65.1@150.25,146.287 C65.1@150.265,146.302 ; C64.1@148.17,140.042 C64.1@148.173,140.042 ; C64.1@148.17,140.042 C64.1@148.173,140.042 ; C64.1@148.17,140.042 148.17,139.928 C64.1@148.173,139.928 ; C64.1@148.173,139.928 C64.1@148.173,140.042 ; C64.1@148.173,139.928 C64.1@148.173,140.042
  Top Layer w0.3: R58.1@146.562,140.042 C64.1@148.17,140.042 ; C64.1@148.17,140.042 148.17,141.97 ; C64.1@148.17,140.042 148.17,141.97 ; 148.17,141.97 148.902,142.702 ; 148.17,141.97 148.902,142.702 ; 148.902,142.702 D3.2@148.902,144.152 148.902,142.702
  Top Layer w0.5: v3(150.14,147.92) 150.251,147.92 150.251,146.302 C65.1@150.265,146.302
  Top Layer w0.8: D3.2@148.902,144.152 150.25,145.5 C65.1@150.25,146.287
  Bottom Layer w0.3: v1(131.86,153.1) 144.99,153.1 v3@150.14,147.95
  Bottom Layer w0.5: v3(150.14,147.92) v3@150.14,147.95
LCD-BL: J2.7 R11.1 | length 158.2
  Top Layer w0.3: J2.7@79.22,79.58 81.99,79.58 82.75,80.34 82.75,83.71 83.92,84.88 89.29,84.88 v1(89.29,84.9) ; R11.1@163.697,150.679 163.697,145.07 166.64,142.127 v1(166.64,139.34)
  Bottom Layer w0.3: v1(89.29,84.9) 149.97,84.9 152.49,87.42 152.49,101.41 155.11,104.03 166.52,104.03 169.81,107.32 169.81,126.82 166.64,129.99 v1(166.64,139.34)
LCD-DITHB: J5.47 R4.2 R5.2 | length 19.3
  Top Layer w0.2: R4.2@140.29,149.69 140.252,149.63 141.847,148.04 R5.2@141.81,147.99 ; R4.2@139.792,149.89 139.83,149.89 R4.2@139.792,149.89 ; R4.2@139.792,149.89 139.792,149.852 R4.2@139.792,149.89
  Top Layer w0.25: J5.47@133.17,155.43 133.17,154.105 134.065,153.21 138.69,153.21 139.881,152.019 ; 139.881,152.019 140.252,151.647 ; 139.881,152.019 140.252,151.647 ; 139.881,152.019 140.252,151.647 ; R4.2@140.252,149.63 R4.2@140.29,149.69 ; R4.2@140.252,149.63 140.252,151.647 ; R4.2@140.252,149.63 140.252,151.647 ; R4.2@140.252,149.63 R4.2@140.29,149.69 ; R4.2@140.252,149.63 R4.2@140.29,149.69 ; R4.2@140.252,149.63 140.252,151.647
LCD-L/R: J5.39 R6.2 R7.2 | length 7.6
  Top Layer w0.25: R6.2@128.53,149.69 128.53,150.9 129.17,151.54 J5.39@129.17,155.43
  Top Layer w0.3: R6.2@128.53,149.69 128.53,149.83 129.84,149.83 R7.2@129.84,149.69
LCD-MODE: J5.8 R2.2 R3.2 | length 8.3
  Top Layer w0.2: R3.2@111.07,148.41 111.012,148.41 111.012,148.468 112.557,150.012 112.557,150.07 R2.2@112.5,150.07
  Top Layer w0.25: R2.2@112.5,150.07 112.51,150.07 112.51,151.902 113.67,153.062 J5.8@113.67,155.43
LCD-U/D: J5.40 R8.2 R9.2 | length 10.8
  Top Layer w0.25: J5.40@129.67,155.43 129.67,151.63 130.47,150.83 ; 130.47,150.83 R9.2@131.277,150.023 ; 130.47,150.83 R9.2@131.277,150.023 ; 130.47,150.83 R9.2@131.277,150.023 ; R9.2@131.277,149.818 R9.2@131.28,149.69 ; R9.2@131.277,149.818 R9.2@131.277,150.023 ; R9.2@131.277,149.818 R9.2@131.277,150.023 ; R9.2@131.277,149.818 R9.2@131.28,149.69 ; R9.2@131.277,149.818 R9.2@131.28,149.69 ; R9.2@131.277,149.818 R9.2@131.277,150.023
  Top Layer w0.3: R9.2@131.28,149.69 131.277,149.818 R8.2@132.629,149.818
LCD-VCOM: C48.1 C49.1 C71.1 C73.1 J5.6 J5.46 R46.1 U9.2 | length 60.2
  Top Layer w0.2: C48.1@103.603,150.499 C48.1@103.706,150.601 ; v3(112.44,157.34) v3@112.67,157.34
  Top Layer w0.25: 111.29,152.23 112.67,153.61 J5.6@112.67,155.43 v3@112.67,157.34 ; v3(132.61,157.18) 132.67,157.22 J5.46@132.67,155.43 132.67,153.78 133.75,152.7 138.03,152.7 138.965,151.765 C73.1@138.965,149.627
  Top Layer w0.3: C71.1@107.92,150.092 107.92,151.55 108.6,152.23 111.29,152.23
  Top Layer w0.5: U9.2@98.32,152.555 98.32,156.78 R46.1@98.342,156.887 ; C49.1@105.395,150.711 105.305,150.601 106.358,150.601 106.867,150.092 C71.1@107.92,150.092
  Top Layer w0.6: U9.2@98.32,152.555 98.387,152.488 98.387,151.073 98.961,150.499 C48.1@103.603,150.499 ; C48.1@103.706,150.601 105.305,150.601 C49.1@105.395,150.711
  Bottom Layer w0.25: v3@132.45,157.34 v3(132.61,157.18)
  Bottom Layer w0.35: v3(112.44,157.34) v3@132.45,157.34
LCD-VGH: C57.1 C58.1 D2.2 J5.41 R56.1 | length 68.9
  Top Layer w0.2: J5.41@130.17,155.43 130.17,153.1 130.83,152.44 v1(130.83,152.34) ; R56.1@155.066,110.009 155.066,109.946 C57.1@156.576,109.946 ; 156.576,115.179 156.576,115.252 D2.2@156.084,115.745 ; D2.2@155.666,115.779 D2.2@156.084,115.745 ; D2.2@155.666,115.779 D2.2@156.084,115.745 ; D2.2@155.666,115.779 D2.2@156.05,115.779 ; D2.2@155.666,115.779 D2.2@156.05,115.779 ; D2.2@155.666,115.779 D2.2@156.084,115.745 ; D2.2@156.05,115.779 D2.2@156.084,115.745 ; D2.2@156.05,115.779 D2.2@156.084,115.745 ; D2.2@156.05,115.779 D2.2@156.073,115.779 ; D2.2@156.05,115.779 D2.2@156.073,115.779 ; D2.2@156.073,115.779 D2.2@156.084,115.745 ; D2.2@156.073,115.779 D2.2@156.084,115.745
  Top Layer w0.3: C57.1@156.576,109.946 156.576,115.179
  Top Layer w0.5: v3(156.08,117.88) v3@156.08,117.889
  Top Layer w0.8: D2.2@155.666,115.779 156.138,116.25 157.049,116.25 157.559,116.76 C58.1@157.559,117.889 v3@156.08,117.889
  Bottom Layer w0.25: v3(156.08,117.88) v3@156.085,117.885
  Bottom Layer w0.3: v1(130.83,152.34) 131.75,151.42 141.74,151.42 146.47,146.69 146.47,133.62 151.03,129.06 151.03,122.94 v3@156.085,117.885
LCD-VGL: C67.1 C68.1 C70.1 D4.1 J5.42 R60.1 | length 63.1
  Top Layer w0.2: C70.1@134.37,149.589 134.37,151.27 134.121,151.519 133.419,151.519 132.758,152.18 v1(131.98,152.18) ; D4.1@152.65,130.3 D4.1@152.61,130.3 154.31,130.3 155.21,129.4 C67.1@155.21,124.297 155.21,124.48 153.69,124.48 R60.1@153.581,124.327 ; 130.67,153.441 v1@131.931,152.18 ; 130.67,153.441 J5.42@130.67,155.43 130.67,153.441 ; 130.67,153.441 v1@131.931,152.18 ; v1@131.931,152.18 v1(131.98,152.18) ; v1@131.931,152.18 v1(131.98,152.18)
  Top Layer w0.8: D4.1@152.65,130.3 152.65,132.04 v3@153.225,132.615 ; v3(153.17,132.67) v3@153.225,132.615 ; v3@153.225,132.615 v3@153.27,132.66 ; v3@153.225,132.615 v3@153.27,132.66 ; v3@153.27,132.66 C68.1@154.343,132.66 v3@153.27,132.66
  Bottom Layer w0.3: v1(131.98,152.18) 142.37,152.18 147.45,147.1 147.45,135.45 149.34,133.56 152.28,133.56 v3(153.17,132.67)
  other v1: 131.98,152.18
LCD_B0: RP11.4 U1.99 | length 18.1
  Top Layer w0.2: U1.99@129.44,126.76 129.44,129.25 132.71,132.52 137.2,132.52 138.896,134.216 RP11.4@138.896,138.34
LCD_B1: RP11.3 U1.100 | length 17.9
  Top Layer w0.2: U1.100@129.04,126.76 129.04,129.416 132.634,133.01 136.94,133.01 138.096,134.166 RP11.3@138.096,138.34
LCD_B2: RP11.2 U1.101 | length 17.5
  Top Layer w0.2: U1.101@128.64,126.76 128.64,129.581 132.599,133.54 136.52,133.54 137.296,134.316 RP11.2@137.296,138.34
LCD_B3: RP11.1 U1.102 | length 17
  Top Layer w0.2: U1.102@128.24,126.76 128.24,129.766 132.544,134.07 135.98,134.07 136.496,134.586 RP11.1@136.496,138.34
LCD_B4: RP12.4 U1.103 | length 13.6
  Top Layer w0.2: U1.103@127.84,126.76 127.84,129.931 132.65,134.741 132.65,138.331 RP12.4@132.657,138.331
LCD_B5: RP12.3 U1.104 | length 13.4
  Top Layer w0.2: U1.104@127.44,126.76 127.44,130.097 131.86,134.517 131.86,137.129 131.857,137.132 RP12.3@131.857,138.331
LCD_B6: RP12.2 U1.105 | length 13.2
  Top Layer w0.2: U1.105@127.04,126.76 127.04,130.263 131.04,134.263 131.04,138.314 RP12.2@131.057,138.331
LCD_B7: RP12.1 U1.106 | length 13.1
  Top Layer w0.2: U1.106@126.64,126.76 126.64,130.428 130.29,134.078 130.29,138.298 130.29,138.331 RP12.1@130.257,138.331
LCD_DE: R17.2 U1.95 | length 11.9
  Top Layer w0.2: U1.95@132.04,124.56 133.683,124.56 135.783,126.66 141.07,126.66 141.63,127.22 141.63,127.6 R17.2@141.63,128.4
LCD_G0: RP9.4 U1.107 | length 15.6
  Top Layer w0.2: U1.107@126.24,126.76 126.24,130.594 129.237,133.591 129.237,137.76 129.21,137.788 129.21,137.809 128.31,138.708 RP9.4@126.329,138.708
LCD_G1: RP9.3 U1.108 | length 15.9
  Top Layer w0.2: RP9.3@125.529,138.358 125.529,137.6 125.71,137.419 128.575,137.419 128.837,137.157 128.837,133.757 125.84,130.76 U1.108@125.84,126.76
LCD_G2: RP9.2 U1.112 | length 13
  Top Layer w0.2: U1.112@124.24,126.76 124.24,132.62 123.46,133.4 123.46,137.15 123.69,137.38 124.61,137.38 124.76,137.53 124.76,138.327 RP9.2@124.729,138.358
LCD_G3: RP9.1 U1.113 | length 13
  Top Layer w0.2: 123.076,138.434 123.06,138.418 123.06,133.234 123.84,132.454 U1.113@123.84,126.76 ; 123.078,138.434 123.352,138.708 RP9.1@123.929,138.708
LCD_G4: RP10.4 U1.114 | length 14
  Top Layer w0.2: RP10.4@119.736,138.717 120.69,138.717 122.66,136.747 122.66,133.05 123.44,132.27 U1.114@123.44,126.76
LCD_G5: RP10.3 U1.115 | length 14.5
  Top Layer w0.2: RP10.3@118.936,138.367 118.936,137.617 119.053,137.5 121.08,137.5 122.26,136.32 122.26,132.884 123.04,132.104 U1.115@123.04,126.76
LCD_G6: RP10.2 U1.116 | length 14.8
  Top Layer w0.2: RP10.2@118.136,138.367 118.136,137.424 118.57,136.99 120.82,136.99 121.86,135.95 121.86,132.719 122.64,131.939 U1.116@122.64,126.76
LCD_G7: RP10.1 U1.117 | length 15.3
  Top Layer w0.2: RP10.1@117.336,138.367 117.336,137.014 117.78,136.57 120.586,136.57 121.46,135.696 121.46,132.55 122.24,131.77 U1.117@122.24,126.76
LCD_HSYNC: R19.2 U1.94 | length 13.8
  Top Layer w0.2: U1.94@132.04,124.16 133.849,124.16 135.949,126.26 142.62,126.26 143.12,126.76 143.12,127.6 143.12,128.4 R19.2@143.1,128.4
LCD_PCLK: R16.2 U1.96 | length 10.1
  Top Layer w0.2: U1.96@132.04,124.96 133.47,124.96 135.58,127.07 139.82,127.07 140.15,127.4 140.15,128.4 R16.2@140.13,128.4
LCD_R0: RP7.4 U1.118 | length 17.8
  Top Layer w0.2: RP7.4@113.019,138.746 113.54,138.746 116.11,136.176 116.11,136.16 119.2,136.16 121.04,134.32 121.04,132.39 121.84,131.59 U1.118@121.84,126.76
LCD_R1: RP7.3 U1.119 | length 18.1
  Top Layer w0.2: RP7.3@112.219,138.396 112.219,138.022 112.651,137.59 113.24,137.59 115.08,135.75 119.044,135.75 120.62,134.174 120.62,132.244 121.44,131.424 U1.119@121.44,126.76
LCD_R2: RP7.2 U1.120 | length 18.6
  Top Layer w0.2: RP7.2@111.419,138.396 111.419,137.646 111.925,137.14 112.94,137.14 114.74,135.34 118.888,135.34 120.19,134.038 120.19,132.109 121.04,131.259 U1.120@121.04,126.76
LCD_R3: RP7.1 U1.123 | length 17
  Top Layer w0.2: RP7.1@110.62,138.396 110.62,137.35 111.24,136.73 112.565,136.73 115.18,134.115 115.195,134.115 117.81,131.5 119.14,131.5 119.84,130.8 U1.123@119.84,126.76
LCD_R4: RP8.4 U1.124 | length 21.2
  Top Layer w0.2: RP8.4@106.06,138.35 106.11,138.3 106.11,137.02 107.02,136.11 112.55,136.11 117.63,131.03 119.03,131.03 119.44,130.62 U1.124@119.44,126.76
LCD_R5: RP8.3 U1.125 | length 21.5
  Top Layer w0.2: RP8.3@105.26,138.35 105.31,138.3 105.31,136.77 106.39,135.69 112.404,135.69 117.464,130.63 118.586,130.63 119.04,130.176 U1.125@119.04,126.76
LCD_R6: RP8.2 U1.126 | length 21.9
  Top Layer w0.2: RP8.2@104.51,138.3 104.46,138.35 104.46,136.66 105.91,135.21 112.319,135.21 113.84,133.689 113.84,133.68 115.08,132.44 115.089,132.44 117.299,130.23 118.367,130.23 118.64,129.957 U1.126@118.64,126.76
LCD_R7: RP8.1 U1.127 | length 22.4
  Top Layer w0.2: RP8.1@103.66,138.35 103.71,138.3 103.71,135.99 104.89,134.81 112.153,134.81 112.938,134.025 112.938,134.016 117.124,129.83 118.03,129.83 118.24,129.62 U1.127@118.24,126.76
LCD_VSYNC: R18.2 U1.93 | length 16.3
  Top Layer w0.2: U1.93@132.04,123.76 134.014,123.76 136.114,125.86 143.97,125.86 144.57,126.46 144.57,128.4 R18.2@144.56,128.4 ; R18.2@144.56,128.4 144.56,128.77 R18.2@144.56,128.4
LDO_CAP12: C10.1 C11.1 C12.1 C13.1 C14.1 C15.1 U1.4 U1.63 U1.111 | length 55.9
  Top Layer w0.2: C11.1@109.83,120.972 109.787,120.972 C10.1@109.787,122.326 109.851,122.39 110.67,122.39 112.04,123.76 U1.4@116.04,123.76 116.76,123.76 117.79,124.79 121.275,124.79 121.305,124.82 124.64,124.82 ; C14.1@125.605,133.846 124.364,133.846 124.36,133.842 C15.1@124.32,133.882 ; 129.84,116.11 U1.63@129.84,110.76 129.84,104.24 130.68,103.4 C12.1@130.68,102.417 131.386,102.417 131.87,102.42 C13.1@131.88,102.437 ; C15.1@124.308,133.894 C15.1@124.32,133.882 ; C15.1@124.308,133.894 C15.1@124.32,133.882 ; C15.1@124.308,133.894 C15.1@124.32,133.882 ; C15.1@124.308,133.894 124.32,133.894 C15.1@124.32,133.882 ; C15.1@124.32,133.882 124.32,133.11 124.64,132.79 U1.111@124.64,126.76 ; 124.64,124.82 U1.111@124.64,126.76 ; 124.64,124.82 U1.111@124.64,126.76
  Top Layer w0.4: 124.64,124.82 124.64,121.31 129.84,116.11
LEDA: BL.2 C54.1 C55.1 D1.2 J5.1 J5.2 J6.2 U2.5 | length 118.8
  Top Layer w0.2: 110.655,154.205 110.67,154.19 110.655,154.205
  Top Layer w0.25: v1(108.32,166.75) 108.32,161.72 110.67,159.37 110.67,156.68 ; v1(109.93,170.19) 109.86,170.19 109.84,170.17 115.41,170.17 116.22,170.98 J6.2@116.22,172.24 ; 110.17,154.21 J5.1@110.17,155.43 ; 110.17,154.21 J5.1@110.17,155.43 ; 110.17,154.21 J5.1@110.17,155.43 ; J5.1@110.17,155.43 110.17,156.68 110.67,156.68 ; J5.2@110.67,155.43 110.67,156.68 ; J5.2@110.67,155.43 110.67,154.19 J5.2@110.67,155.43 ; J5.2@110.67,155.43 110.67,156.68
  Top Layer w0.35: v4(109.02,154.65) 109.54,154.09 110.01,154.09 110.165,154.205 ; 110.165,154.205 110.655,154.205 110.165,154.205 ; 110.165,154.205 110.17,154.21 ; 110.165,154.205 110.17,154.21 ; 110.165,154.205 110.17,154.21
  Top Layer w0.6: D1.2@166.71,155.11 166.86,154.96 166.86,154.84 168.87,152.83 168.87,151.72 168.58,151.43 U2.5@167.57,151.43 ; BL.2@167.03,165.61 166.98,165.56 166.98,162.217 C55.1@167.097,162.1
  Top Layer w0.8: D1.2@166.71,155.11 166.71,155.113 167.097,155.5 C55.1@167.097,162.1
  Bottom Layer w0.25: v1(108.32,166.75) 108.32,168.58 v1(109.93,170.19)
  Bottom Layer w0.6: v4(109.02,154.65) 109.02,154.71 138.99,154.71 141.17,156.89 141.17,160.64 144.51,163.98 154.1,163.98 155.92,162.16 163.58,162.16 BL.2@167.03,165.61
LEDK: BL.1 J5.3 J5.4 J6.1 R52.1 R55.1 U2.3 | length 147
  Top Layer w0.2: 111.155,153.795 J5.3@111.155,155.415 ; 111.155,153.795 J5.3@111.155,155.415 ; 111.155,153.795 J5.3@111.155,155.415 ; J5.3@111.155,155.415 J5.3@111.17,155.43 ; J5.3@111.155,155.415 J5.3@111.17,155.43 ; J5.3@111.155,155.415 J5.3@111.17,155.43
  Top Layer w0.25: v1(109.11,167.52) 109.11,161.84 111.17,159.78 111.17,156.71 ; v1(111.75,170.86) 115.33,170.86 115.72,171.25 J6.1@115.72,172.24 ; R52.1@170.86,159.29 170.87,159.3 R52.1@170.97,159.3 ; 111.17,156.71 J5.3@111.17,155.43 111.17,156.71 ; 111.17,156.71 111.67,156.71 J5.4@111.67,155.43 ; J5.4@111.67,155.43 111.67,154.11 J5.4@111.67,155.43
  Top Layer w0.3: v4(107.6,153.61) v4@107.81,153.4 ; 111.55,153.96 111.67,154.11 111.55,153.96 ; 111.55,153.96 111.32,153.96 111.55,153.96
  Top Layer w0.35: v4@107.81,153.4 110.76,153.4 111.155,153.795 ; 111.155,153.795 111.32,153.96 111.155,153.795
  Top Layer w0.8: U2.3@170.11,152.382 170.11,153.34 169.31,154.14 169.31,157.74 R52.1@170.86,159.29 ; 160.33,166.71 BL.1@160.33,165.61 160.33,166.71 ; 160.33,166.71 161.46,167.84 ; 160.33,166.71 161.46,167.84 ; 161.46,167.84 169.19,167.84 ; 161.46,167.84 169.19,167.84 ; 169.19,167.84 170.86,166.17 ; 169.19,167.84 170.86,166.17 ; R52.1@170.86,159.29 R55.1@170.86,161.3 ; R52.1@170.86,159.29 R55.1@170.86,161.3 ; R55.1@170.86,161.3 170.86,166.17 ; R55.1@170.86,161.3 170.86,166.17 ; R55.1@170.86,161.3 R55.1@170.97,161.41 R55.1@170.86,161.3
  Bottom Layer w0.25: v1(109.11,167.52) 109.11,168.22 v1(111.75,170.86)
  Bottom Layer w0.6: v4(107.6,153.61) 107.6,155.44 108.15,155.99 138.55,155.99 139.99,157.43 139.99,161.37 144.23,165.61 BL.1@160.33,165.61
LT768_CS#: J4.17 RP2.3 U1.13 | length 71.5
  Top Layer w0.2: RP2.3@96.581,110.015 96.586,110.02 v1(97.6,110.02) ; v1(112.44,119.98) 112.44,120.02 112.58,120.16 U1.13@116.04,120.16
  Bottom Layer w0.2: v1(97.6,110.02) 98.16,110.02 98.935,109.245 100.505,109.245 101.05,109.79 101.05,112.49 103.2,114.64 111.44,114.64 112.42,115.62 112.42,119.96 v1(112.44,119.98)
  Bottom Layer w0.3: 87.94,117.59 95.51,110.02 ; 87.94,117.59 J4.17@79.22,117.59 87.94,117.59 ; 87.94,117.59 95.51,110.02 ; 95.51,110.02 v1(97.6,110.02) 95.51,110.02
  other v1: 97.6,110.02
LT768_DB0: J4.1 RP6.3 U1.18 | length 109.7
  Top Layer w0.2: RP6.3@96.55,130.82 v1(97.37,130.82) ; v1(105.75,118.82) 111.72,118.82 112.38,118.16 U1.18@116.04,118.16
  Bottom Layer w0.2: v1(97.37,130.82) 97.37,130.81 98.39,130.81 99.03,130.17 99.03,120.9 99.06,120.9 100.22,119.74 104.83,119.74 v1(105.75,118.82)
  Bottom Layer w0.3: 80.7,158.23 82.29,156.64 ; 80.7,158.23 J4.1@79.22,158.23 80.7,158.23 ; 80.7,158.23 82.29,156.64 ; 82.29,155.11 85.3,152.1 ; 82.29,155.11 82.29,156.64 ; 82.29,155.11 85.3,152.1 ; 82.29,155.11 82.29,156.64 ; 85.3,152.1 88.34,152.1 ; 85.3,152.1 88.34,152.1 ; 88.34,152.1 90.27,150.17 ; 88.34,152.1 90.27,150.17 ; 90.27,134.16 93.61,130.82 ; 90.27,134.16 90.27,150.17 ; 90.27,134.16 93.61,130.82 ; 90.27,134.16 90.27,150.17 ; 93.61,130.82 v1(97.37,130.82) 93.61,130.82
  other v1: 97.37,130.82
LT768_DB1: J4.2 RP6.2 U1.19 | length 106.2
  Top Layer w0.2: RP6.2@96.55,130.02 v1(97.35,130.02) ; v1(104.71,118.79) 105.3,118.2 111.77,118.2 112.21,117.76 U1.19@116.04,117.76
  Bottom Layer w0.2: v1(97.35,130.02) 98.28,130.02 98.62,129.68 98.62,120.744 100.024,119.34 104.16,119.34 v1(104.71,118.79)
  Bottom Layer w0.3: 80.42,155.69 84.8,151.31 ; 80.42,155.69 J4.2@79.22,155.69 80.42,155.69 ; 80.42,155.69 84.8,151.31 ; 84.8,151.31 87.77,151.31 ; 84.8,151.31 87.77,151.31 ; 87.77,151.31 89.52,149.56 ; 87.77,151.31 89.52,149.56 ; 89.52,133.44 92.94,130.02 ; 89.52,133.44 89.52,149.56 ; 89.52,133.44 92.94,130.02 ; 89.52,133.44 89.52,149.56 ; 92.94,130.02 v1(97.35,130.02) 92.94,130.02
  other v1: 97.35,130.02
LT768_DB2: J4.3 RP6.1 U1.20 | length 103.7
  Top Layer w0.2: RP6.1@96.55,129.22 v1(97.38,129.22) ; v1(103.71,118.76) 104.68,117.79 111.55,117.79 111.98,117.36 U1.20@116.04,117.36
  Bottom Layer w0.2: v1(97.38,129.22) 97.89,129.22 98.21,128.9 98.21,120.29 99.74,118.76 v1(103.71,118.76)
  Bottom Layer w0.3: 81.22,153.15 J4.3@79.22,153.15 81.22,153.15 ; 81.22,153.15 83.91,150.46 ; 81.22,153.15 83.91,150.46 ; 83.91,150.46 86.5,150.46 ; 83.91,150.46 86.5,150.46 ; 86.5,150.46 88.67,148.29 ; 86.5,150.46 88.67,148.29 ; 88.67,132.86 88.67,148.29 ; 88.67,132.86 92.314,129.216 ; 88.67,132.86 92.314,129.216 ; 88.67,132.86 88.67,148.29 ; 92.314,129.216 96.701,129.216 ; 92.314,129.216 96.701,129.216 ; 96.701,129.216 96.705,129.22 ; 96.701,129.216 96.705,129.22 ; 96.705,129.22 v1(97.38,129.22) 96.705,129.22
  other v1: 97.38,129.22
LT768_DB3: J4.4 RP5.4 U1.21 | length 87.3
  Top Layer w0.2: RP5.4@96.55,126.44 97.32,126.44 v1(97.33,126.45) ; v1(97.33,126.45) 98.82,126.45 ; v1(97.33,126.45) 98.82,126.45 ; 98.82,126.45 100.51,124.76 ; 98.82,126.45 100.51,124.76 ; 100.51,121.18 100.51,124.76 ; 100.51,121.18 104.3,117.39 ; 100.51,121.18 104.3,117.39 ; 100.51,121.18 100.51,124.76 ; 104.3,117.39 111.26,117.39 ; 104.3,117.39 111.26,117.39 ; 111.26,117.39 111.69,116.96 ; 111.26,117.39 111.69,116.96 ; 111.69,116.96 U1.21@116.04,116.96 111.69,116.96
  Bottom Layer w0.3: J4.4@79.22,150.61 82.24,150.61 83.23,149.62 85.65,149.62 87.92,147.35 87.92,132.18 93.65,126.45 v1(97.33,126.45)
  other v1: 97.33,126.45
LT768_DB4_SCS#: J3.1 J4.5 RP5.3 U1.22 | length 117.9
  Top Layer w0.2: RP5.3@96.55,125.64 97.34,125.64 v1(97.35,125.65) ; v1(97.35,125.65) 98.8,125.65 ; v1(97.35,125.65) 98.8,125.65 ; 98.8,125.65 100.06,124.39 ; 98.8,125.65 100.06,124.39 ; 100.06,120.98 104.05,116.99 ; 100.06,120.98 100.06,124.39 ; 100.06,120.98 104.05,116.99 ; 100.06,120.98 100.06,124.39 ; 104.05,116.99 111.09,116.99 ; 104.05,116.99 111.09,116.99 ; 111.09,116.99 111.52,116.56 ; 111.09,116.99 111.52,116.56 ; 111.52,116.56 U1.22@116.04,116.56 111.52,116.56
  Top Layer w0.25: J4.5@79.22,148.07 80.97,148.07 81.54,148.64 v1(81.54,160.46)
  Bottom Layer w0.25: J3.1@79.22,172.24 82.29,172.24 84.56,169.97 84.56,161.51 83.51,160.46 v1(81.54,160.46)
  Bottom Layer w0.3: J4.5@79.22,148.07 84.96,148.07 87.24,145.79 87.24,131.86 93.45,125.65 v1(97.35,125.65)
  other v1: 97.35,125.65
